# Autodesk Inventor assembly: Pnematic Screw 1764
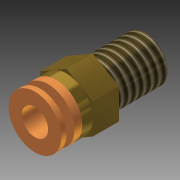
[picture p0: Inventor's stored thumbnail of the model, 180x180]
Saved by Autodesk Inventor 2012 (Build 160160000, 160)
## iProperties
Created: 2010-02
Part Number: Pnematic Screw 1764
Document SubType Name: Assembly
Designer: clee1
Author: clee1
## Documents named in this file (3)
- R:\CAD Archives\Pneumatics_1764\Soloniod_1764\Pneumatic_Screw_1764\Pneumatic_Screw_1764.iam
- R:\CAD Archives\Pneumatics_1764\Soloniod_1764\Pneumatic_Screw_1764\Pneumatic_Screw_Part_1_1764.ipt
- R:\CAD Archives\Pneumatics_1764\Soloniod_1764\Pneumatic_Screw_1764\Pneumatic_Screw_Part_2_1764.ipt
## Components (2 placed, 2 different names)
1. Pneumatic_Screw_Part_1_1764:1 — Insert:1
2. Pneumatic_Screw_Part_2_1764:1 — Insert:1
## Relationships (1: Insert 1)
- Insert:1: Pneumatic_Screw_Part_1_1764:1 ↔ Pneumatic_Screw_Part_2_1764:1
